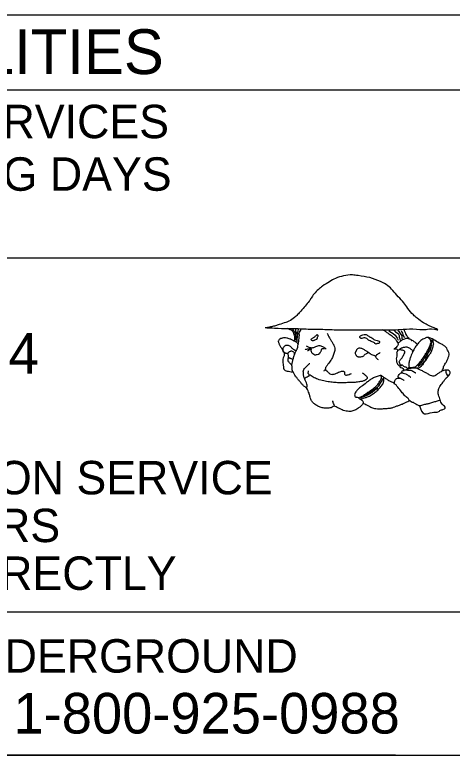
# Model space of a CAD drawing. Extents: x 0.4 to 34.4, y -2.1 to 19.9.
# Drawn here: x 6.568 to 8.399, y 0.086 to 3.186 of the extents above; entities that cross this region are included whole.
import ezdxf

# ---------------------------------------------------------------- set-up
doc = ezdxf.new("R2010")
doc.units = 0
doc.layers.add('SH_Data', color=7, linetype='Continuous')

msp = doc.modelspace()

# ---------------------------------------------------------------- linework, layer by layer
at = {"layer": 'SH_Data'}
for p, q in [((3.4251, 3.186), (8.6251, 3.186)), ((8.6251, 2.8706), (3.4251, 2.8706)), ((3.4251, 2.1681), (8.6251, 2.1681)), ((7.7293, 1.8705), (7.7336, 1.8662)), ((7.7336, 1.8662), (7.7386, 1.8602)), ((7.7386, 1.8602), (7.7411, 1.8535)), ((7.7436, 1.8705), (7.7436, 1.8629)), ((7.7436, 1.8629), (7.7461, 1.8561)), ((7.7521, 1.8621), (7.7512, 1.8552)), ((7.7539, 1.8688), (7.7521, 1.8621)), ((8.1337, 1.8629), (8.1447, 1.8561)), ((8.1557, 1.8637), (8.1616, 1.8586)), ((8.171, 1.8637), (8.1752, 1.8594)), ((8.1861, 1.8637), (8.1878, 1.8569)), ((7.7411, 1.8535), (7.742, 1.8442)), ((7.742, 1.8442), (7.742, 1.8306)), ((7.742, 1.8306), (7.7436, 1.8231)), ((7.7479, 1.8476), (7.7453, 1.8306)), ((7.7453, 1.8306), (7.7471, 1.8231)), ((7.7461, 1.8561), (7.7479, 1.8476)), ((7.7504, 1.8409), (7.7487, 1.8239)), ((7.7512, 1.8493), (7.7504, 1.8409)), ((7.7512, 1.8552), (7.7512, 1.8493)), ((8.1447, 1.8561), (8.1523, 1.851)), ((8.1523, 1.851), (8.1599, 1.8442)), ((8.1599, 1.8442), (8.1693, 1.8315)), ((8.1616, 1.8586), (8.1726, 1.8518)), ((8.1693, 1.8315), (8.1726, 1.8231)), ((8.1726, 1.8518), (8.1777, 1.8434)), ((8.1752, 1.8594), (8.1811, 1.8518)), ((8.1777, 1.8434), (8.1777, 1.8358)), ((8.1777, 1.8358), (8.1802, 1.829)), ((8.1811, 1.8518), (8.1878, 1.8417)), ((8.1878, 1.8569), (8.1904, 1.8526)), ((8.1878, 1.8417), (8.1878, 1.8323)), ((8.1878, 1.8323), (8.1896, 1.8281)), ((8.1904, 1.8526), (8.1929, 1.8476)), ((8.1929, 1.8476), (8.1972, 1.8383)), ((8.1972, 1.8383), (8.2014, 1.8358)), ((7.7471, 1.8231), (7.7471, 1.8222)), ((7.7487, 1.8239), (7.7487, 1.8171)), ((8.1802, 1.829), (8.1811, 1.8222)), ((3.4251, 0.686), (8.6251, 0.686)), ((3.4251, 0.086), (8.6251, 0.086)), ((3.8882, 0.086), (8.1621, 0.086)), ((8.1621, 0.086), (3.8882, 0.086))]:
    msp.add_line(p, q, dxfattribs=at)
for points in [[(7.6236, 1.8747), (7.6397, 1.875), (7.6699, 1.8734), (7.7277, 1.8731), (7.7804, 1.8708), (7.8419, 1.8696), (7.9045, 1.8676), (7.969, 1.8671), (8.036, 1.8671), (8.1099, 1.8666), (8.181, 1.8683), (8.2343, 1.8705), (8.2896, 1.8688), (8.3252, 1.8691), (8.3381, 1.8679), (8.3378, 1.8681), (8.3196, 1.8765), (8.3003, 1.8847), (8.2791, 1.8961), (8.2524, 1.9155), (8.2364, 1.9296), (8.2139, 1.9568), (8.197, 1.9801), (8.1735, 2.0058), (8.1502, 2.0318), (8.1297, 2.0517), (8.0991, 2.0693), (8.0545, 2.0854), (8.005, 2.0941), (7.9811, 2.0967), (7.9443, 2.0927), (7.9106, 2.0822), (7.8853, 2.0686), (7.8566, 2.0501), (7.8387, 2.0356), (7.821, 2.0176), (7.8083, 1.9991), (7.8004, 1.9871), (7.7831, 1.9665), (7.7657, 1.9458), (7.7519, 1.9306), (7.7385, 1.9189), (7.7156, 1.903), (7.7031, 1.898), (7.6749, 1.8888), (7.6587, 1.8838), (7.6419, 1.8797), (7.6261, 1.8767), (7.6166, 1.8751)], [(7.7097, 1.8746), (7.7137, 1.8714), (7.7197, 1.8688), (7.7241, 1.8671), (7.7294, 1.8626), (7.7316, 1.8609), (7.7343, 1.8536), (7.7347, 1.8525), (7.7366, 1.8462), (7.7381, 1.8419), (7.7393, 1.8375), (7.7394, 1.8338), (7.7391, 1.8313), (7.7391, 1.8262), (7.7391, 1.8239), (7.7391, 1.8214), (7.7391, 1.8202), (7.7425, 1.8183), (7.7466, 1.8156), (7.7493, 1.8126), (7.7535, 1.8061)], [(7.7915, 1.6213), (7.7893, 1.623), (7.7829, 1.6276), (7.7744, 1.635), (7.7669, 1.6434), (7.7578, 1.6542), (7.75, 1.6646), (7.7428, 1.6731), (7.7372, 1.6825), (7.7319, 1.6931), (7.7296, 1.6989), (7.7283, 1.7118), (7.7285, 1.7251), (7.7316, 1.7377), (7.7351, 1.7515), (7.7379, 1.7594), (7.7396, 1.7659), (7.7443, 1.776), (7.7493, 1.7867), (7.7515, 1.7904), (7.7531, 1.8), (7.7556, 1.8122), (7.7572, 1.8246), (7.7585, 1.836), (7.7591, 1.8452), (7.7593, 1.8565), (7.765, 1.8661), (7.7657, 1.8717)], [(8.1058, 1.8677), (8.1111, 1.8656), (8.1229, 1.8581), (8.1337, 1.8505), (8.1479, 1.84), (8.1565, 1.8329), (8.1651, 1.823), (8.1707, 1.8134), (8.1715, 1.8116), (8.1715, 1.8105), (8.1744, 1.8125), (8.1773, 1.815), (8.1821, 1.8189), (8.1923, 1.8262), (8.2003, 1.8296), (8.2058, 1.8317), (8.2154, 1.8311), (8.2243, 1.8276), (8.2283, 1.8246), (8.2269, 1.8226), (8.2306, 1.824), (8.2376, 1.8191), (8.2406, 1.8169), (8.2461, 1.8131), (8.2491, 1.8104), (8.2511, 1.8039)], [(8.1964, 1.8693), (8.1965, 1.8681), (8.1986, 1.8636), (8.2006, 1.8591), (8.2029, 1.8531), (8.2052, 1.8469), (8.2101, 1.8405), (8.2149, 1.8354), (8.2168, 1.8331), (8.2176, 1.8302)], [(7.737, 1.8197), (7.7356, 1.8206), (7.7299, 1.8237), (7.7248, 1.8263), (7.7207, 1.828), (7.7129, 1.8309), (7.706, 1.8326), (7.6971, 1.8331), (7.689, 1.8323), (7.6839, 1.8313), (7.6776, 1.8285), (7.6747, 1.826), (7.6711, 1.8212), (7.6707, 1.8187), (7.6711, 1.8171), (7.6731, 1.8113), (7.675, 1.806), (7.6769, 1.8014), (7.6803, 1.7958), (7.6848, 1.7896), (7.6894, 1.7814), (7.6912, 1.7788), (7.6927, 1.7763), (7.6954, 1.7712), (7.6958, 1.7679), (7.6956, 1.7616), (7.6916, 1.7498), (7.6896, 1.7371), (7.6901, 1.7284), (7.6914, 1.7176), (7.6926, 1.7109), (7.6946, 1.7016), (7.6968, 1.699), (7.7039, 1.6956), (7.7135, 1.6936), (7.7249, 1.691), (7.7304, 1.691), (7.7345, 1.6912)], [(7.8331, 1.8448), (7.8301, 1.8437), (7.8276, 1.8417), (7.8244, 1.8387), (7.8196, 1.8351), (7.8156, 1.8319), (7.8108, 1.8292), (7.8076, 1.8269), (7.8106, 1.8235), (7.8136, 1.8223), (7.8169, 1.8223), (7.8208, 1.8235), (7.8245, 1.8251), (7.8307, 1.828), (7.8333, 1.8293), (7.8347, 1.8321), (7.8357, 1.8366), (7.8372, 1.8406), (7.8364, 1.8448), (7.8337, 1.8456), (7.8323, 1.8465)], [(7.8756, 1.8533), (7.8783, 1.8468), (7.8848, 1.8338), (7.8911, 1.8239), (7.8983, 1.8123), (7.9041, 1.8008), (7.9075, 1.7902), (7.9066, 1.7768), (7.9002, 1.7601), (7.8974, 1.7515), (7.8885, 1.736), (7.8819, 1.7276), (7.8754, 1.7177), (7.8711, 1.7125), (7.8679, 1.7056), (7.8654, 1.6989), (7.8625, 1.6959), (7.8611, 1.6944)], [(8.0124, 1.839), (8.0175, 1.8431), (8.0248, 1.8463), (8.0348, 1.848), (8.0418, 1.8454), (8.0477, 1.8414), (8.0581, 1.8356), (8.0662, 1.8311), (8.0693, 1.8277), (8.0737, 1.8255), (8.0856, 1.8221), (8.0929, 1.82), (8.0945, 1.8177), (8.0952, 1.8143), (8.091, 1.8101), (8.0883, 1.8096), (8.0836, 1.8085), (8.0799, 1.8076), (8.0758, 1.81), (8.0736, 1.8127), (8.0687, 1.8156), (8.0598, 1.8188), (8.0521, 1.8221), (8.0465, 1.8264), (8.041, 1.8301), (8.0339, 1.833), (8.0247, 1.8319), (8.0181, 1.8302), (8.0162, 1.8317), (8.0125, 1.8348), (8.0116, 1.8373), (8.0128, 1.8393)], [(8.3566, 1.6954), (8.3611, 1.7031), (8.3629, 1.7116), (8.3715, 1.7271), (8.3786, 1.7397), (8.3829, 1.7513), (8.3861, 1.7626), (8.3845, 1.7715), (8.3785, 1.7848), (8.3731, 1.7944), (8.3635, 1.8013), (8.3578, 1.8052), (8.3452, 1.8115), (8.3215, 1.8255), (8.2948, 1.835), (8.2882, 1.8335), (8.2839, 1.8313), (8.2758, 1.8276), (8.2681, 1.8223), (8.2551, 1.8084), (8.2446, 1.7943), (8.2361, 1.7794), (8.2296, 1.766), (8.2253, 1.7556), (8.2211, 1.7417), (8.2181, 1.728), (8.2178, 1.7189), (8.219, 1.7121), (8.2231, 1.7093), (8.2278, 1.7088), (8.2326, 1.7093), (8.2381, 1.7096), (8.2407, 1.7101), (8.2469, 1.714), (8.2546, 1.7216), (8.2686, 1.7367), (8.2785, 1.7505), (8.2891, 1.7673), (8.2974, 1.7825), (8.3041, 1.7971), (8.3089, 1.8097), (8.3106, 1.8154), (8.3082, 1.8246), (8.296, 1.835)], [(7.7472, 1.7793), (7.7468, 1.78), (7.7441, 1.7802), (7.7401, 1.7814), (7.7372, 1.7826), (7.732, 1.7868), (7.7282, 1.7908), (7.7233, 1.7952), (7.7193, 1.7979), (7.7133, 1.801), (7.7071, 1.8016), (7.7023, 1.8016), (7.699, 1.8001), (7.6961, 1.7976), (7.695, 1.7968), (7.694, 1.7951), (7.6918, 1.7912), (7.69, 1.7859), (7.69, 1.7851), (7.6894, 1.7794)], [(7.8715, 1.786), (7.8674, 1.7896), (7.8574, 1.7956), (7.85, 1.7988), (7.8429, 1.8), (7.8349, 1.7989), (7.8268, 1.7952), (7.8216, 1.7931), (7.8147, 1.7911), (7.8085, 1.7911), (7.7996, 1.7935), (7.7885, 1.7983)], [(8.1715, 1.8105), (8.1723, 1.8051), (8.1702, 1.8006), (8.1641, 1.7931), (8.1607, 1.7906), (8.1568, 1.7872), (8.1556, 1.7866), (8.1575, 1.7872), (8.1611, 1.7877), (8.1652, 1.7875), (8.169, 1.7851), (8.1698, 1.7801), (8.1687, 1.7759), (8.1676, 1.7734), (8.1662, 1.7702)], [(8.3171, 1.8258), (8.3178, 1.8206), (8.3191, 1.8139), (8.3202, 1.8088), (8.3186, 1.8006), (8.3182, 1.7947), (8.3154, 1.788), (8.3122, 1.779), (8.3094, 1.7714), (8.3051, 1.765), (8.299, 1.7563), (8.2936, 1.7467), (8.2871, 1.738), (8.2835, 1.733), (8.2791, 1.7268), (8.2773, 1.7242), (8.2723, 1.7176), (8.2694, 1.7139), (8.264, 1.7096), (8.2585, 1.7071), (8.2493, 1.7064)], [(8.3111, 1.8258), (8.3123, 1.8205), (8.3124, 1.8146), (8.31, 1.805), (8.309, 1.7965), (8.304, 1.7877), (8.2975, 1.7776), (8.2932, 1.7698), (8.2882, 1.7569), (8.2828, 1.7487), (8.2793, 1.7429), (8.2753, 1.7384), (8.2685, 1.7302), (8.2633, 1.7258), (8.2579, 1.719), (8.2565, 1.7159), (8.2598, 1.7146), (8.2627, 1.7173), (8.2674, 1.7215), (8.2769, 1.7288), (8.2891, 1.7426), (8.2991, 1.7701), (8.3085, 1.7846), (8.3122, 1.8058)], [(7.712, 1.7666), (7.711, 1.7671), (7.7057, 1.7672), (7.7031, 1.7681), (7.6991, 1.7709), (7.6943, 1.774), (7.6897, 1.7808)], [(7.739, 1.7636), (7.7393, 1.7656), (7.7385, 1.769), (7.7356, 1.7733), (7.7306, 1.7766), (7.7256, 1.7776), (7.7218, 1.7764), (7.7181, 1.7752), (7.7145, 1.7731), (7.7127, 1.7711), (7.7116, 1.7702), (7.7112, 1.7686), (7.7112, 1.7655), (7.7114, 1.763), (7.7118, 1.759), (7.7126, 1.7539), (7.7145, 1.7508), (7.7178, 1.7491), (7.7215, 1.748), (7.7237, 1.7473), (7.7271, 1.7451), (7.7316, 1.7426)], [(7.8066, 1.7897), (7.8026, 1.7881), (7.7971, 1.7864), (7.7912, 1.7854), (7.7857, 1.7851), (7.7831, 1.7854)], [(7.8106, 1.7914), (7.8045, 1.7858), (7.8016, 1.783), (7.794, 1.7788), (7.7932, 1.7786)], [(7.8103, 1.7891), (7.8096, 1.7886), (7.8082, 1.7844), (7.8075, 1.7785), (7.8086, 1.7756), (7.8106, 1.7717), (7.8154, 1.7675), (7.8232, 1.7626), (7.8277, 1.7629), (7.8336, 1.7637), (7.8431, 1.7679), (7.8441, 1.7689), (7.8456, 1.7712), (7.8496, 1.7763), (7.8506, 1.7793), (7.8524, 1.7852), (7.8535, 1.7872), (7.8597, 1.7883), (7.8648, 1.7886)], [(8.0796, 1.7552), (8.0758, 1.7581), (8.0744, 1.7584), (8.0714, 1.7596), (8.0632, 1.7621), (8.0577, 1.765), (8.0551, 1.7669), (8.0495, 1.7706), (8.0424, 1.7758), (8.0381, 1.7789), (8.0324, 1.7831), (8.0269, 1.7862), (8.0206, 1.7885), (8.0139, 1.7902), (8.0076, 1.7901), (8.0022, 1.7876), (7.9993, 1.7841), (7.9981, 1.7821), (7.9964, 1.7776), (7.9932, 1.7706), (7.9932, 1.7676), (7.9951, 1.7631), (7.9993, 1.7573), (8.0033, 1.7548), (8.0078, 1.7539), (8.0122, 1.7536), (8.0203, 1.7547), (8.0269, 1.7564), (8.0308, 1.7614), (8.0386, 1.7667), (8.0425, 1.769), (8.0466, 1.7709)], [(8.0974, 1.7712), (8.0952, 1.7692), (8.0923, 1.7676), (8.0857, 1.7639), (8.085, 1.7631), (8.0828, 1.7617), (8.0787, 1.7569), (8.0781, 1.7544), (8.0807, 1.7498), (8.0841, 1.7465), (8.0886, 1.7431)], [(8.167, 1.7688), (8.1678, 1.761), (8.1657, 1.7516), (8.1652, 1.7401), (8.1686, 1.7271), (8.1785, 1.7164), (8.1825, 1.7169), (8.1865, 1.7177), (8.1796, 1.7138), (8.1941, 1.7044), (8.1949, 1.6943)], [(8.1694, 1.7772), (8.1712, 1.7792), (8.1756, 1.7837), (8.1786, 1.7856), (8.1873, 1.791), (8.1924, 1.7931), (8.1968, 1.7943), (8.2049, 1.7954), (8.209, 1.7951), (8.2148, 1.7934), (8.2186, 1.7916), (8.2245, 1.788), (8.2286, 1.7851), (8.2327, 1.7789), (8.2316, 1.7764)], [(8.1854, 1.7171), (8.1824, 1.7186), (8.181, 1.7229), (8.1778, 1.7301), (8.1785, 1.7364), (8.1811, 1.7406), (8.1846, 1.7447), (8.189, 1.7501), (8.1929, 1.7563), (8.1965, 1.7633), (8.2001, 1.7706), (8.2004, 1.7731), (8.2007, 1.7756), (8.1977, 1.7788), (8.1933, 1.7806), (8.1896, 1.7817), (8.1836, 1.7826), (8.1793, 1.7831), (8.1741, 1.7821)], [(7.7286, 1.7172), (7.7274, 1.7197), (7.7245, 1.7217), (7.7189, 1.7273), (7.7158, 1.7311), (7.7128, 1.7354), (7.7121, 1.7392), (7.7116, 1.7426), (7.7127, 1.7466), (7.7131, 1.7486), (7.7137, 1.7514)], [(7.9052, 1.5501), (7.9048, 1.5493), (7.9004, 1.5454), (7.8928, 1.541), (7.8873, 1.5401), (7.877, 1.539), (7.8666, 1.5388), (7.8501, 1.5417), (7.8361, 1.5477), (7.8226, 1.5566), (7.8125, 1.5665), (7.8057, 1.5801), (7.8033, 1.5888), (7.7995, 1.6015), (7.7956, 1.6117), (7.7907, 1.6213), (7.79, 1.6227), (7.7906, 1.6269), (7.7916, 1.6348), (7.7893, 1.6444), (7.784, 1.656), (7.7791, 1.6662), (7.777, 1.6781), (7.7765, 1.6871), (7.7757, 1.6921), (7.7781, 1.7006), (7.785, 1.7092), (7.7948, 1.7193), (7.7999, 1.7244), (7.8024, 1.7264)], [(8.0261, 1.558), (8.0283, 1.5586), (8.0373, 1.5547), (8.0431, 1.5522), (8.0543, 1.5456), (8.0691, 1.5396), (8.0798, 1.5371), (8.0931, 1.5359), (8.1111, 1.5371), (8.1225, 1.5376), (8.1402, 1.5396), (8.1537, 1.5429), (8.1644, 1.5471), (8.1782, 1.5517), (8.1893, 1.5562), (8.1985, 1.5604), (8.2086, 1.5656), (8.2181, 1.5698), (8.2203, 1.5715), (8.2229, 1.5693), (8.2318, 1.5647), (8.2445, 1.5585), (8.2566, 1.5516), (8.2636, 1.5501), (8.281, 1.5546), (8.2952, 1.5573), (8.3091, 1.5612), (8.3264, 1.5662), (8.3415, 1.5714), (8.3481, 1.5746), (8.3453, 1.5835), (8.3418, 1.5942), (8.3402, 1.6036), (8.3422, 1.6173), (8.3479, 1.6302), (8.3595, 1.6468), (8.3666, 1.6564), (8.3757, 1.6676), (8.3881, 1.6796), (8.389, 1.6921), (8.3819, 1.6975), (8.3737, 1.6986), (8.3643, 1.6971), (8.3558, 1.6934), (8.3431, 1.6861), (8.3379, 1.6822), (8.3296, 1.6761), (8.3223, 1.6727), (8.3137, 1.6742), (8.3031, 1.679), (8.289, 1.6872), (8.2778, 1.693), (8.2633, 1.7001), (8.2519, 1.7046), (8.2433, 1.7081), (8.2348, 1.7093)], [(8.1824, 1.7186), (8.1891, 1.7206), (8.1931, 1.7165), (8.1983, 1.7129), (8.2028, 1.7117), (8.2065, 1.7109), (8.2106, 1.706), (8.2139, 1.7071), (8.2201, 1.7111)], [(8.2048, 1.6987), (8.2056, 1.6993), (8.2089, 1.7015), (8.2125, 1.7031), (8.2169, 1.7048), (8.2268, 1.7071), (8.2349, 1.7081), (8.2393, 1.7079), (8.2456, 1.7077)], [(7.8006, 1.679), (7.7995, 1.6798), (7.7991, 1.6751), (7.7966, 1.6714), (7.7875, 1.6667), (7.7787, 1.6631)], [(7.8006, 1.679), (7.7968, 1.683), (7.7961, 1.6866), (7.7971, 1.6909), (7.7974, 1.6946)], [(8.0224, 1.6868), (8.0279, 1.6848), (8.034, 1.6786), (8.0385, 1.6743), (8.0436, 1.6676), (8.0406, 1.66), (8.0336, 1.6551), (8.0215, 1.6513), (8.0082, 1.6488), (7.987, 1.6464), (7.9696, 1.6462), (7.9506, 1.6455), (7.9287, 1.6451), (7.9078, 1.6466), (7.8853, 1.649), (7.8614, 1.6531), (7.8358, 1.66), (7.8166, 1.6691), (7.8006, 1.679)], [(7.8679, 1.7021), (7.8706, 1.6986), (7.8777, 1.691), (7.8825, 1.6864), (7.8874, 1.6825), (7.8958, 1.6805), (7.9021, 1.6813), (7.9087, 1.6826), (7.9141, 1.6856), (7.9231, 1.6893), (7.9328, 1.6931), (7.9383, 1.6938), (7.9483, 1.6906), (7.9486, 1.6813), (7.9507, 1.6787), (7.9562, 1.6776), (7.9636, 1.6792), (7.9721, 1.6821), (7.9768, 1.6848)], [(8.1577, 1.6446), (8.1562, 1.645), (8.1504, 1.6461), (8.1436, 1.6497), (8.1336, 1.654), (8.1218, 1.6621), (8.1099, 1.6696), (8.0985, 1.676), (8.097, 1.6756), (8.0808, 1.6706), (8.0654, 1.6637), (8.0537, 1.6565), (8.0407, 1.6459), (8.0185, 1.629), (8.0047, 1.6179), (7.9956, 1.6072), (7.991, 1.5993), (7.9907, 1.5914), (7.9929, 1.5869), (8, 1.5846), (8.0091, 1.5835), (8.0114, 1.5846), (8.022, 1.5887), (8.029, 1.593), (8.0424, 1.6033), (8.0574, 1.6127), (8.0737, 1.6251), (8.0843, 1.6346), (8.0901, 1.6427), (8.0958, 1.6517), (8.1019, 1.6615), (8.1029, 1.6702), (8.0987, 1.6746)], [(8.1781, 1.6646), (8.1756, 1.6665), (8.1736, 1.669), (8.1731, 1.6725), (8.1775, 1.6801), (8.1822, 1.6856), (8.1877, 1.6864), (8.1932, 1.6861), (8.2043, 1.6826), (8.2085, 1.6804), (8.2147, 1.6759), (8.2185, 1.6739), (8.2251, 1.669), (8.2258, 1.669)], [(8.1925, 1.6856), (8.1891, 1.6879), (8.1881, 1.6915), (8.1912, 1.6965), (8.1931, 1.698), (8.1993, 1.6988), (8.2074, 1.699), (8.2162, 1.6984), (8.2261, 1.6981), (8.234, 1.6943), (8.2406, 1.6896), (8.2436, 1.6881), (8.247, 1.6864)], [(8.38, 1.6741), (8.3777, 1.6794), (8.374, 1.688), (8.3737, 1.6969)], [(8.0156, 1.5821), (8.0331, 1.5896), (8.0462, 1.5954), (8.0604, 1.6029), (8.0728, 1.6121), (8.0801, 1.6206), (8.0906, 1.6312), (8.0966, 1.6408), (8.1036, 1.6509), (8.1078, 1.6635), (8.1043, 1.6546), (8.1011, 1.6497), (8.0966, 1.6421), (8.092, 1.6334), (8.0822, 1.6239), (8.075, 1.6183), (8.0669, 1.6136), (8.0549, 1.6071), (8.0465, 1.6013), (8.0366, 1.5955), (8.0286, 1.5906), (8.0896, 1.6233)], [(8.0145, 1.5769), (8.0203, 1.5781), (8.0357, 1.5831), (8.0481, 1.5875), (8.0657, 1.5976), (8.0806, 1.6084), (8.0936, 1.6216), (8.1064, 1.6371), (8.1121, 1.6496), (8.1125, 1.6671)], [(8.2181, 1.5698), (8.2185, 1.5718), (8.2098, 1.5831), (8.1964, 1.5959), (8.184, 1.6118), (8.1675, 1.6316), (8.1586, 1.6401), (8.1549, 1.6423), (8.1577, 1.6446), (8.1581, 1.6477), (8.1581, 1.6502), (8.1591, 1.6531), (8.1623, 1.6596), (8.1645, 1.6621), (8.1671, 1.6637), (8.1744, 1.6648), (8.1829, 1.6642), (8.1896, 1.6602), (8.1944, 1.6576), (8.1977, 1.6548)], [(7.996, 1.5863), (8.0015, 1.585), (8.0093, 1.5801), (8.0107, 1.5781), (8.0197, 1.5738), (8.0216, 1.5706), (8.0249, 1.5679), (8.0265, 1.5627), (8.0269, 1.558)], [(8.0261, 1.558), (8.0218, 1.5529), (8.0164, 1.5471), (8.0069, 1.5401), (8, 1.535), (7.9916, 1.5306), (7.9831, 1.5277), (7.9744, 1.5256), (7.9656, 1.5256), (7.9556, 1.5268), (7.9431, 1.5294), (7.9326, 1.5342), (7.9223, 1.5396), (7.9133, 1.5439), (7.9066, 1.5493), (7.9025, 1.5587), (7.8994, 1.5666), (7.9001, 1.57)], [(8.2615, 1.5489), (8.2835, 1.5151), (8.3148, 1.521), (8.3427, 1.5251), (8.3478, 1.5286), (8.3604, 1.5337), (8.3698, 1.5396), (8.3587, 1.5548), (8.3478, 1.5743)]]:
    msp.add_spline(points, degree=3, dxfattribs=at)

# ---------------------------------------------------------------- texts
for s, height, p in [('UNDERGROUND UTILITIES', 0.1875, (3.9457, 2.9379)), ('CONTACT BOTH SERVICES', 0.14, (4.7377, 2.6693)), ('CALL TWO WORKING DAYS', 0.14, (4.7382, 2.4493)), ('1-800-362-2764', 0.17, (5.0501, 1.6831)), ('OHIO UTILITIES PROTECTION SERVICE', 0.14, (4.0901, 1.1781)), ('NON-MEMBERS', 0.14, (5.3324, 0.9781)), ('MUST BE CALLED DIRECTLY', 0.14, (4.6545, 0.7781)), ('OIL & GAS PRODUCERS UNDERGROUND', 0.14, (4.0284, 0.4317)), ('1-800-925-0988', 0.17, (6.5619, 0.1767))]:
    msp.add_text(s, height=height, dxfattribs=at).set_placement(p)

doc.saveas('drawing.dxf')
